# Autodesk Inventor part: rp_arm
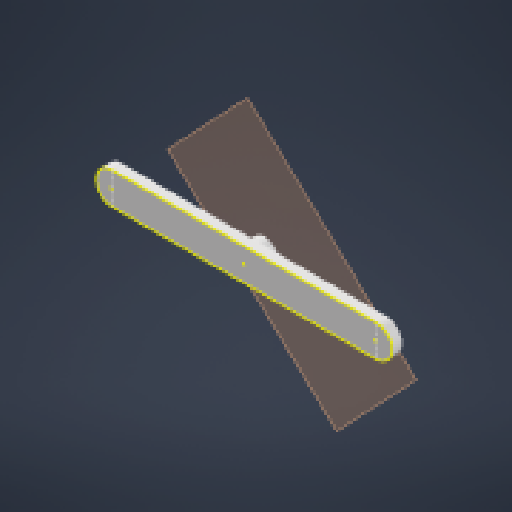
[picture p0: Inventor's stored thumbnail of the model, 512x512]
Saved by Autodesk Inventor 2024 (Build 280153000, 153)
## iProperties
Created: 2023-09
Part Number: rp_arm
Material: Generic
Document SubType Name: Modeling
Designer: mammothbane
Density: 1 g/cm^3
Appearance: Default
Author: mammothbane
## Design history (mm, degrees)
sketch "Sketch1"
  geometry: C1 r 12.5 at (-17.096, -19.55); 1 further point
  constraints: 1 centre point, 1 coincident
  dimensions: "d0" = 25 diameter of C1
extrude "Extrusion1" new body sketch "Sketch1" distance "d1" = 10; taper "d2" = 0 deg
sketch "Sketch2"
  geometry: L1 (-125, 0)-(125, 0); L2 (-125, -15)-(125, -15); L3 (125, 15)-(-125, 15); C1 r 12.5 at (0, 0) reference; A1 r 15 centre (-125, 0) between (-125, 15) and (-125, -15); A2 r 15 centre (125, 0) between (125, -15) and (125, 15); 1 further point
  constraints: 8 end point, 4 point on circle, 4 tangent, 2 centre point, 1 horizontal, 1 midpoint, 1 parallel
  dimensions: "d3" = 30 distance between parallel lines of L2 L3; "d4" = 250 distance of L1.start L1.end
extrude "Extrusion2" join sketch "Sketch2" distance "d5" = 10; taper "d6" = 0 deg
sketch "Sketch3"
  geometry: L1 (125, 15)-(-125, 15) reference; L2 (-125, -15)-(125, -15) reference; L3 (125, 15)-(125, -15); L4 (125, 15)-(-125, 15) reference; L5 (-125, 15)-(-125, -15); A1 r 15 centre (125, 0) between (125, -15) and (125, 15) reference; A2 r 15 centre (-125, 0) between (-125, 15) and (-125, -15) reference; A3 r 15 centre (125, 0) between (125, -15) and (125, 15) reference; 1 further point
  constraints: 4 end point, 2 perpendicular
  node "Projected Loop1"
body "Solid1"
